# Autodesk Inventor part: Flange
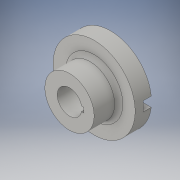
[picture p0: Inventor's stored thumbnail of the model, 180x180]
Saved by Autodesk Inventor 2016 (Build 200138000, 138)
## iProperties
Created: 2020-03
Part Number: Flange
Material: Generic
Document SubType Name: Modeling
Designer: Furqan
Density: 1 g/cm^3
Appearance: Default
Author: Furqan
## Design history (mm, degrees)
sketch "Sketch1"
  geometry: L1 (15.24, 0)-(50.8, 0); L2 (50.8, 0)-(50.8, 20.32); L3 (50.8, 20.32)-(30.48, 20.32); L4 (30.48, 20.32)-(30.48, 50.8); L5 (30.48, 50.8)-(15.24, 50.8); L6 (15.24, 50.8)-(15.24, 0); L7 (0, 0)-(0, 16.074) reference
  constraints: 14 end point, 5 perpendicular, 2 vertical, 1 horizontal
  dimensions: "d0" = 50.8 distance of L5.end L1.start; "d1" = 20.32 distance of L1.end L2.end; "d3" = 101.6 diameter of L2 L7; "d4" = 60.96 diameter of L4 L7; "d5" = 30.48 diameter of L6 L7
revolve "Revolution1" sketch "Sketch1" stored, may be unused: angle "d6" = 90 deg
sketch "Sketch2"
  geometry: L1 (52.07, 5.994)-(-52.07, 5.994); L2 (-52.07, 5.994)-(-52.07, -5.994); L3 (-52.07, -5.994)-(52.07, -5.994); L4 (52.07, -5.994)-(52.07, 5.994); L5 (52.07, 5.994)-(-52.07, -5.994); L6 (-52.07, 5.994)-(52.07, -5.994); 1 further point
  constraints: 12 end point, 2 midpoint, 2 parallel, 1 horizontal, 1 perpendicular
  dimensions: "d7" = 104.14 distance of L3.end L2.end; "d8" = 11.9888 distance of L2.end L1.end
extrude "Extrusion1" cut sketch "Sketch2" distance "d9" = 10.16; taper "d10" = 0 deg
sketch "Sketch3"
  geometry: L1 (14.942, 2.997)-(17.94, 2.997); L2 (17.94, 2.997)-(17.94, -2.997); L3 (17.94, -2.997)-(14.942, -2.997); C1 r 15.24 at (0, 0) reference; A1 r 15.24 centre (0, 0) between (14.942, -2.997) and (14.942, 2.997); 1 further point
  constraints: 6 end point, 2 perpendicular, 2 point on circle, 1 centre point, 1 coincident, 1 horizontal, 1 parallel
  dimensions: "d12" = 30.48 diameter of A1; "d13" = 5.9944 distance of L1.end L2.end; "d14" = 2.9972 distance of L1.start L1.end
extrude "Extrusion2" cut sketch "Sketch3" stored distance "d15" = 10.16; taper "d16" = 0 deg
fillet "Fillet1" dims "d17" = 5.08
body "Solid1"
